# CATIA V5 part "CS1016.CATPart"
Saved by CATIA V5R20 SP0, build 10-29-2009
Part number: CS1016
Revision: 4
Definition: design
Nomenclature: CS1016
Source: made
Description: NOT SPECIFIED
Bounding box of the stored display mesh (mm): x -15 to 15, y -15 to 15, z -28 to 7.5
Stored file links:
  C:\Users\Raffaele\Desktop\3D X SITO CF\BOLEX\20-TILTED COLUMN SUPPORT\CS1016.CATPart
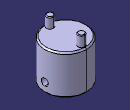
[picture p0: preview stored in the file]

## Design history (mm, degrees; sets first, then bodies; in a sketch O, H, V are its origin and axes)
Body1 "MANIFOLD_SOLID_BREP #691" (main body)
  Solid1: solid without history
